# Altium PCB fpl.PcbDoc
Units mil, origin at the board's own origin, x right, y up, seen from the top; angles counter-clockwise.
Board outline 3900 x 3500 mil, 2 copper layers (Top Layer, Bottom Layer); 34 components, 34 nets, 170 pads, 0 vias.
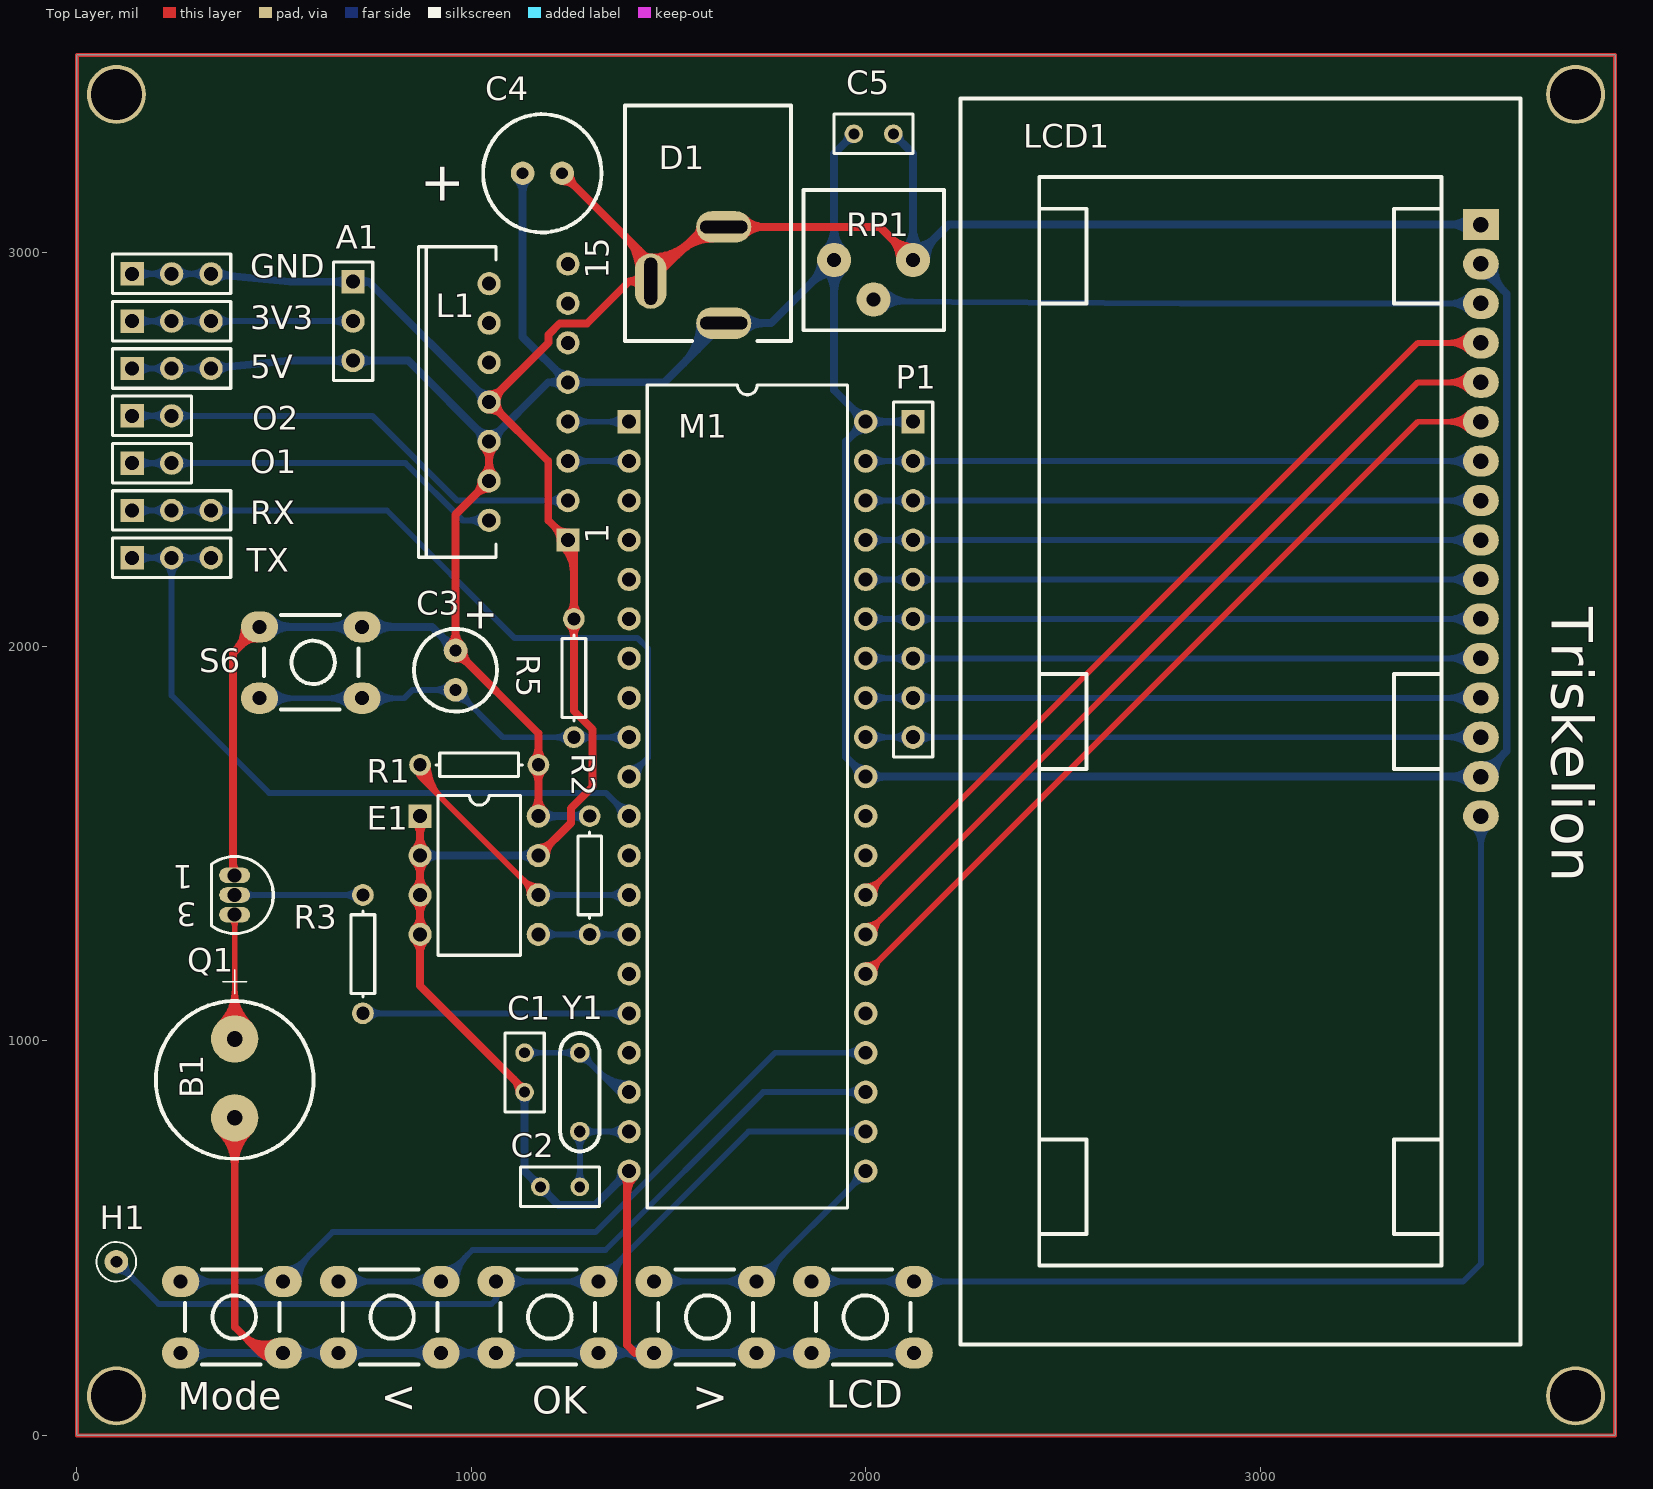
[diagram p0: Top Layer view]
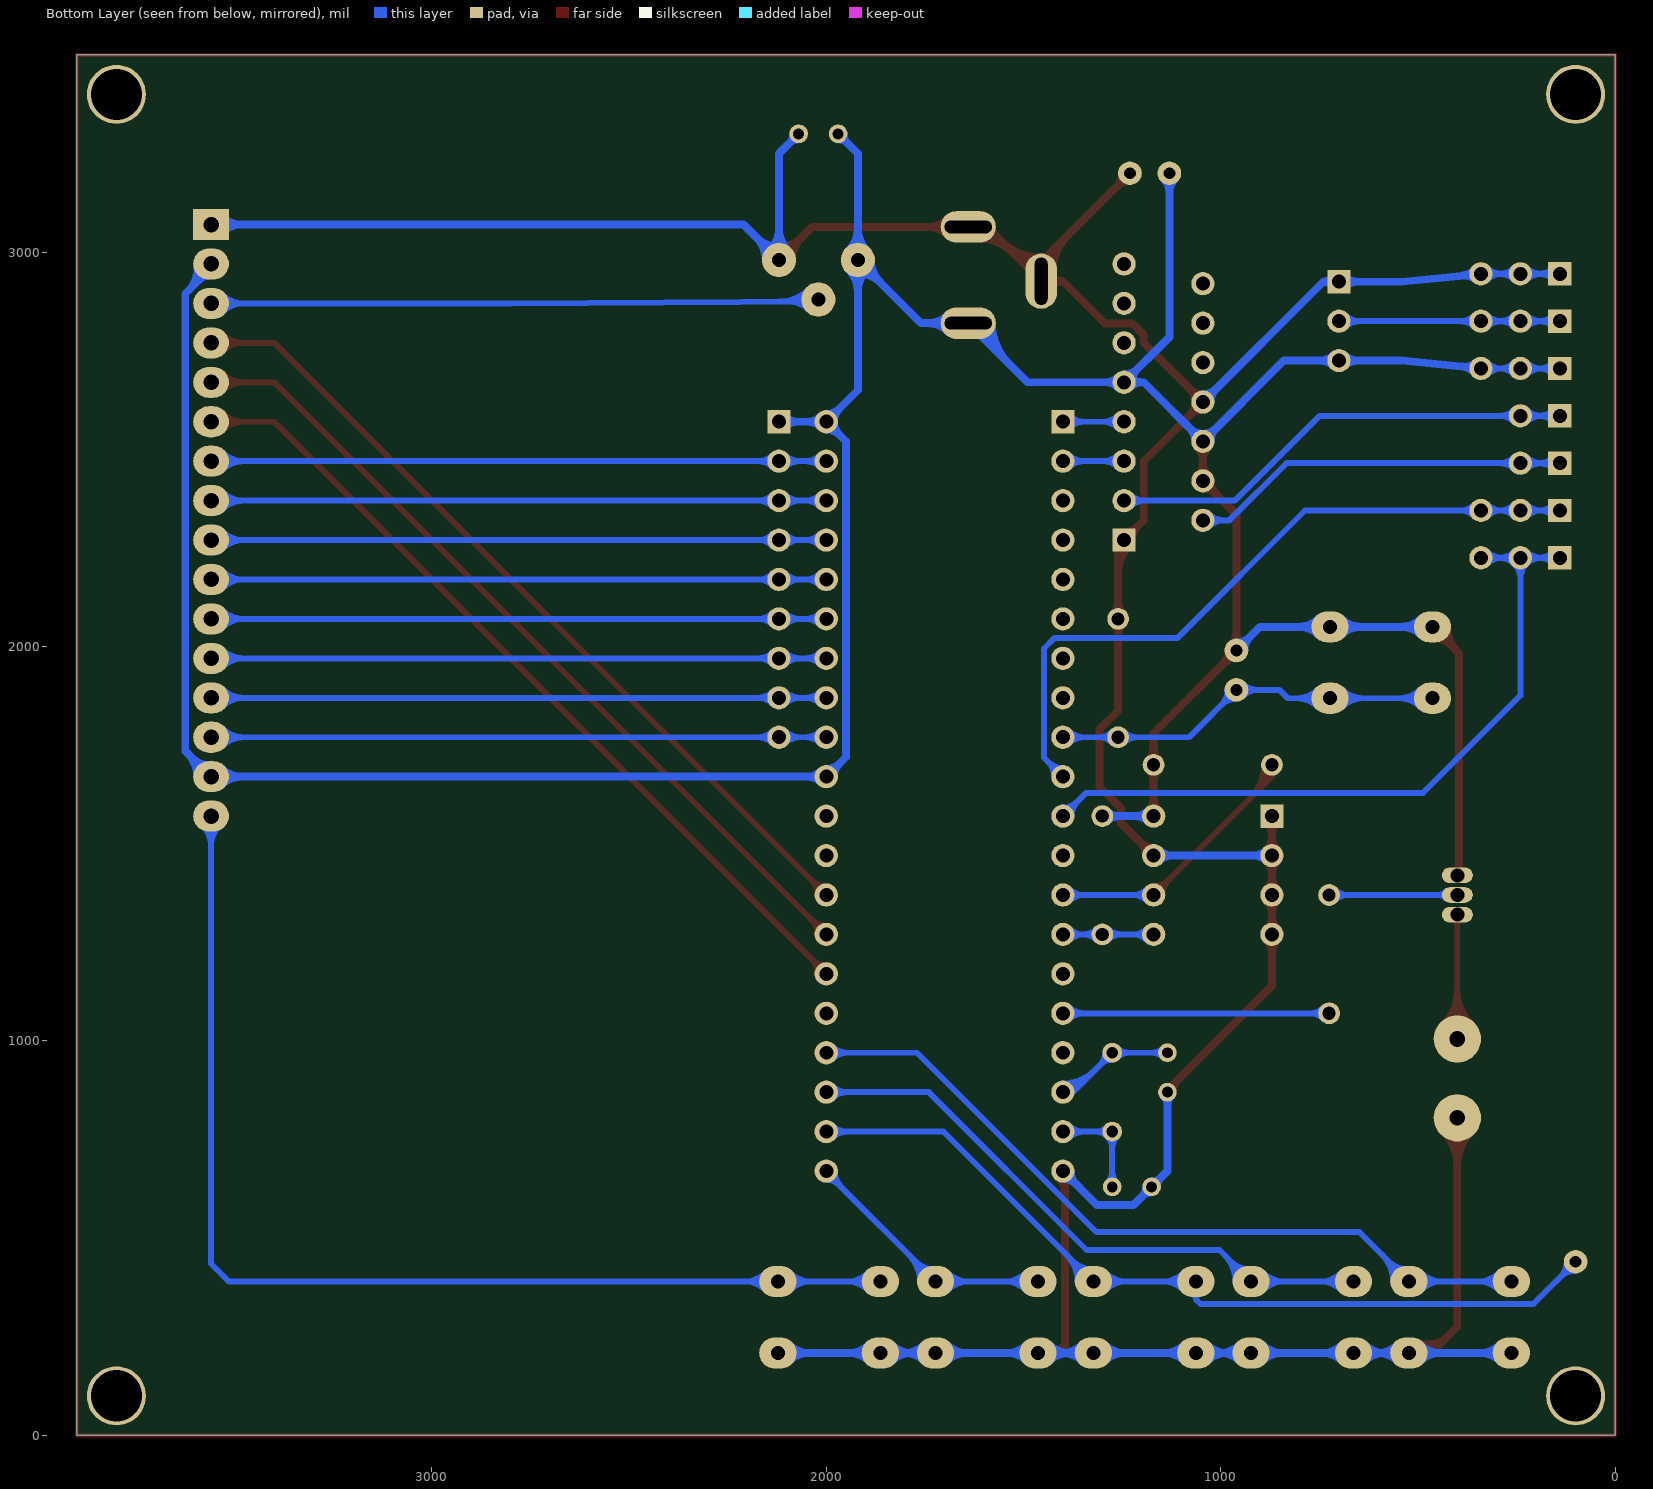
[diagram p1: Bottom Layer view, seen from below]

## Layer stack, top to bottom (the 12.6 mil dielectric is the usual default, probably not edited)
Top Solder: solder mask 0.4, Solder Resist, Dk 3.5
Top Layer: signal copper 1.4
Dielectric1: dielectric 12.6, FR-4, Dk 4.8
Bottom Layer: signal copper 1.4
Bottom Solder: solder mask 0.4, Solder Resist, Dk 3.5

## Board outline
0,0 3900,0 3900,3500 0,3500

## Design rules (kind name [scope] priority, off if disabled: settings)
Clearance [All] p1: gap=10 ignorepadtopadclearanceinfootprint=FALSE except(0: Arc-Hole Track-Hole SMDPad-Hole THPad-Hole Via-Hole Fill-Hole Poly-Hole Region-Hole Text-Hole)
HoleSize [All] p1 off: absolutevalues=TRUE maxlimit=100 minlimit=1 maxpercent=80.000 minpercent=20.000
MinimumSolderMaskSliver [All] p1 off: minsoldermaskwidth=10
PolygonConnect [All] p1: connectstyle=Relief reliefconductorwidth=10 reliefentries=4 polygonreliefangle="90 Angle" airgapwidth=10
RoutingVias [All] p1: holewidth=28 width=50 viastyle="Through Hole" minholewidth=28 minwidth=50 maxholewidth=28 maxwidth=50
SilkToSolderMaskClearance SilkscreenOverComponentPads [IsPad] p1: minsilkscreentomaskgap=5 clearancetoexposedcopper=TRUE
SolderMaskExpansion [All] p1: expansion=4
Width GND [InNet('GND')] p1: maxlimit=25 minlimit=15 preferedwidth=20
Width VCC [InNet('VCC')] p2: maxlimit=25 minlimit=15 preferedwidth=20
Width [All] p3: maxlimit=20 minlimit=10 preferedwidth=15
27 further rules are at their usual default settings.

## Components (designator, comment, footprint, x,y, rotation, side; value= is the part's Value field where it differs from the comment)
3V3 "Header 3" HDR1X3 140,2825 r0 top (schematic designator P3)
5V "Header 3" HDR1X3 140,2705 r0 top (schematic designator P2)
< "switch" switch_4pin 800,300 r0 top (schematic designator S3)
> "switch" switch_4pin 1600,300 r0 top (schematic designator S1)
A1 "3V3" HDR1X3 700,2925 r270 top
B1 "BEEP" BEEP 400,905 r90 top
C1 "Cap" RAD-0.1 1135,920 r90 top
C2 "Cap" RAD-0.1 1225,630 r0 top
C3 "Cap Pol1" ElecCap 960,1940 r180 top
C4 "Cap Pol1" ElecCap470 1180,3200 r90 top
C5 "Cap" RAD-0.1 2020,3300 r0 top
D1 "DC" DC005 1640,3020 r270 top
E1 "E2PROM" DIP-8 1020,1420 r0 top
GND "Header 3" HDR1X3 140,2945 r0 top (schematic designator P4)
H1 "Head1" Head1 100,440 r0 top
L1 "L298N" Multiwatt15V 1145,2620 r90 top
LCD "switch" switch_4pin 2000,300 r0 top (schematic designator S5)
LCD1 "LCD1602" 1602 3560,3070 r270 top
M1 "STC89C52(RC)" 40P6 1700,1620 r270 top
Mode "switch" switch_4pin 400,300 r0 top (schematic designator S4)
O1 "Header 2" HDR1X2 140,2465 r0 top (schematic designator P7)
O2 "Header 2" HDR1X2 140,2585 r0 top (schematic designator P8)
OK "switch" switch_4pin 1200,300 r0 top (schematic designator S2)
P1 "9PIN8" HDR1X9 2120,2570 r270 top
Q1 "2N3906" BCY-W3/E4 400,1370 r180 top
R1 "Res2" AXIAL-0.3 1020,1700 r0 top
R2 "Res2" AXIAL-0.3 1300,1420 r90 top
R3 "Res2" AXIAL-0.3 725,1220 r90 top
R5 "Res2" AXIAL-0.3 1260,1920 r270 top
RP1 "potentiometer" potentionmeter 2020,2980 r0 top
RX "Header 3" HDR1X3 140,2345 r0 top (schematic designator P6)
S6 "switch" switch_4pin 600,1960 r0 top
TX "Header 3" HDR1X3 140,2225 r0 top (schematic designator P5)
Y1 "XTAL" XTAL 1275,870 r270 top

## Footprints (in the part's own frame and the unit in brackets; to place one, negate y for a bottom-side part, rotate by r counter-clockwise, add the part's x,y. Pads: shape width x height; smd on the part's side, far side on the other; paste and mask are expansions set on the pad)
40P6 [mm] "DIP; 40 Leads; Row Spacing 15.24 mm; Pitch 2.54 mm"
  rect 1.5x1.5 hole 0.9: 1(-24.13,-7.62)
  round 1.5 hole 0.9: 2(-21.59,-7.62) 3(-19.05,-7.62) 4(-16.51,-7.62) 5(-13.97,-7.62) 6(-11.43,-7.62) 7(-8.89,-7.62) 8(-6.35,-7.62) 9(-3.81,-7.62) 10(-1.27,-7.62) 11(1.27,-7.62) 12(3.81,-7.62) 13(6.35,-7.62) 14(8.89,-7.62) 15(11.43,-7.62) 16(13.97,-7.62) 17(16.51,-7.62) 18(19.05,-7.62) 19(21.59,-7.62) 20(24.13,-7.62) 21(24.13,7.62) 22(21.59,7.62) 23(19.05,7.62) 24(16.51,7.62) 25(13.97,7.62) 26(11.43,7.62) 27(8.89,7.62) 28(6.35,7.62) 29(3.81,7.62) 30(1.27,7.62) 31(-1.27,7.62) 32(-3.81,7.62) 33(-6.35,7.62) 34(-8.89,7.62) 35(-11.43,7.62) 36(-13.97,7.62) 37(-16.51,7.62) 38(-19.05,7.62) 39(-21.59,7.62) 40(-24.13,7.62)
  silkscreen extent -26.5,-6.45 26.5,6.45
1602 [mm]
  rect 2x2.3 hole 1: 1(0,0)
  oval 2x2.3 hole 1: 2(2.54,0) 3(5.08,0) 4(7.62,0) 5(10.16,0) 6(12.7,0) 7(15.24,0) 8(17.78,0) 9(20.32,0) 10(22.86,0) 11(25.4,0) 12(27.94,0) 13(30.48,0) 14(33.02,0) 15(35.56,0) 16(38.1,0)
  silkscreen extent -8.13,-33.53 72.14,2.54
AXIAL-0.3 [mm] "Axial Device, Thru-Hole; 2 Leads; 0.3 in Pin Spacing"
  round 1.4 hole 0.85: 1(-3.81,0) 2(3.81,0)
  silkscreen extent -2.77,-0.76 2.77,0.76
BCY-W3/E4 [mm] "TO, Flat Index; 3 In-Line, Axial Leads; Body Dia. 4.5mm; Leads 0.51 x 0.48 mm (max)"
  oval 2x1 hole 0.9: 1(0,-1.27) 2(0,0) 3(0,1.27)
  silkscreen extent -2.48,-2.48 1.5,2.48
BEEP [mil] "蜂鸣器"
  round 120 hole 40: 1(100,0) 2(-100,0)
  silkscreen extent -204,-200 275,200
DC005 [mil] "2.1mmDC插座"
  oval 80x140 hole 32 slot 120 at 90 deg: 1(200,0) 3(-44,0)
  oval 140x80 hole 32 slot 120 at 0 deg: 2(93.7,-185)
  silkscreen extent -352,-250 245,170
DIP-8 [mm]
  rect 1.5x1.5 hole 0.9: 1(-3.81,3.81)
  round 1.5 hole 0.9: 2(-3.81,1.27) 3(-3.81,-1.27) 4(-3.81,-3.81) 5(3.81,-3.81) 6(3.81,-1.27) 7(3.81,1.27) 8(3.81,3.81)
  silkscreen extent -2.65,-5.15 2.65,5.15
ElecCap [mil] "10uF电解电容"
  round 60 hole 30: 1(0,-50) 2(0,50)
  silkscreen extent -105,-105 105,105
ElecCap470 [mil] "470uF电解电容"
  round 60 hole 30: 1(0,50) 2(0,-50)
  silkscreen extent -150,-150 150,150
HDR1X2 [mm] "Connector; Header; 2 Position"
  rect 1.5x1.5 hole 0.9: 1(0,0)
  round 1.5 hole 0.9: 2(2.54,0)
  silkscreen extent -1.27,-1.27 3.81,1.27
HDR1X3 [mm] "Connector; Header; 3 Position"
  rect 1.5x1.5 hole 0.9: 1(0,0)
  round 1.5 hole 0.9: 2(2.54,0) 3(5.08,0)
  silkscreen extent -1.27,-1.27 6.35,1.27
HDR1X9 [mm] "Connector; Header; 9 Position"
  rect 1.5x1.5 hole 0.9: 1(0,0)
  round 1.5 hole 0.9: 2(2.54,0) 3(5.08,0) 4(7.62,0) 5(10.16,0) 6(12.7,0) 7(15.24,0) 8(17.78,0) 9(20.32,0)
  silkscreen extent -1.27,-1.27 21.59,1.27
Head1 [mil] "1pin焊盘"
  round 60 hole 30: 1(0,0)
  silkscreen extent -50,-50 50,50
Multiwatt15V [mm] "TO, Thru-Hole, Vertical, Heatsink Mounted; 15 Bent Staggered Leads; Pitch 1.27 mm"
  rect 1.5x1.5 hole 0.9: 1(-8.89,-2.54)
  round 1.5 hole 0.9: 2(-7.62,2.54) 3(-6.35,-2.54) 4(-5.08,2.54) 5(-3.81,-2.54) 6(-2.54,2.54) 7(-1.27,-2.54) 8(0,2.54) 9(1.27,-2.54) 10(2.54,2.54) 11(3.81,-2.54) 12(5.08,2.54) 13(6.35,-2.54) 14(7.62,2.54) 15(8.89,-2.54)
  silkscreen extent -10,2.09 10,7.09
potentionmeter [mm] "电位计"
  round 2.2 hole 0.9: 1(-2.54,0) 2(0,-2.54) 3(2.54,0)
  silkscreen extent -4.52,-4.52 4.52,4.52
RAD-0.1 [mm] "Radial Cap, Thru-Hole; 2 Leads; 0.1 in Pin Spacing"
  round 1.2 hole 0.7: 1(-1.27,0) 2(1.27,0)
  silkscreen extent -2.54,-1.27 2.54,1.27
switch_4pin [mm] "单稳态按钮开关"
  oval 2.4x2 hole 0.9: 0(-3.48,2.286) 1(-3.48,-2.314) 2(3.12,2.286) 3(3.12,-2.314)
  silkscreen extent -3.2,-3.05 2.9,3.05
XTAL [mil] "晶振"
  round 50 hole 30: 1(-100,0) 2(100,0)
  silkscreen extent -150,-50 150,50

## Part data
3V3 5V GND RX TX: "Header, 3-Pin"
< > LCD Mode OK S6: library part Switch_4pin, "单稳态按钮开关"
A1: library part AMS1117, "3.3V电源模块, 5V to 3.3V"
B1: "蜂鸣器"
C1 C2 C5: "Capacitor"
C3 C4: "Polarized Capacitor (Radial)"
D1: "DC插座"
E1: library part AT24C02, "E2PROM,I2C-上拉"
H1: "1pin焊盘"
L1: "电机驱动芯片"
M1: library part STC89C52, "MCU"
O1 O2: "Header, 2-Pin"
P1: "9PIN8排阻"
Q1: "PNP General Purpose Amplifier"
R1 R2 R3 R5: "Resistor"
RP1: library part 电位计, "旋钮式电位计"
Y1: "Crystal Oscillator"

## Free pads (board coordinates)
  round 150 hole 130: 0(100,100) 0(100,3400) 0(3800,100) 0(3800,3400)

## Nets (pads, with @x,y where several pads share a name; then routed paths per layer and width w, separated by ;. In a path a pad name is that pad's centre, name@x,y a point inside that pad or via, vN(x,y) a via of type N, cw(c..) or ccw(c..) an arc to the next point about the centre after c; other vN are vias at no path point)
BEEP: M1.16 R3.1 | length 834.6
  Bottom Layer w15: R3.1 M1.16 ; R3.1@739.18,1055.82 cw(c773.43,1021.57) 773.43,1070 cw(c773.43,1118.43) R3.1@739.18,1084.18 ; M1.16@1384.42,1054.42 ccw(c1346.82,1016.82) 1346.82,1070 ccw(c1346.82,1123.18) M1.16@1384.42,1085.58
D0: LCD1.7 M1.39 P1.2 | length 1995.4
  Bottom Layer w15: M1.39 P1.2 LCD1.7 ; M1.39@2015.58,2454.42 cw(c2053.18,2416.82) 2053.18,2470 cw(c2053.18,2523.18) M1.39@2015.58,2485.58 ; P1.2@2104.42,2454.42 ccw(c2066.82,2416.82) 2066.82,2470 ccw(c2066.82,2523.18) P1.2@2104.42,2485.58 ; P1.2@2135.58,2454.42 cw(c2173.18,2416.82) 2173.18,2470 cw(c2173.18,2523.18) P1.2@2135.58,2485.58 ; LCD1.7@3531.56,2447.46 ccw(c3477.15,2393.06) 3477.15,2470 ccw(c3477.15,2546.94) LCD1.7@3531.56,2492.54 ; LCD1.7@3542.17,2458.07 ccw(c3513.37,2429.27) 3513.37,2470 ccw(c3513.37,2510.73) LCD1.7@3542.17,2481.93
D1: LCD1.8 M1.38 P1.3 | length 1995.4
  Bottom Layer w15: M1.38 P1.3 LCD1.8 ; M1.38@2015.58,2354.42 cw(c2053.18,2316.82) 2053.18,2370 cw(c2053.18,2423.18) M1.38@2015.58,2385.58 ; P1.3@2104.42,2354.42 ccw(c2066.82,2316.82) 2066.82,2370 ccw(c2066.82,2423.18) P1.3@2104.42,2385.58 ; P1.3@2135.58,2354.42 cw(c2173.18,2316.82) 2173.18,2370 cw(c2173.18,2423.18) P1.3@2135.58,2385.58 ; LCD1.8@3531.56,2347.46 ccw(c3477.15,2293.06) 3477.15,2370 ccw(c3477.15,2446.94) LCD1.8@3531.56,2392.54 ; LCD1.8@3542.17,2358.07 ccw(c3513.37,2329.27) 3513.37,2370 ccw(c3513.37,2410.73) LCD1.8@3542.17,2381.93
D2: LCD1.9 M1.37 P1.4 | length 1995.4
  Bottom Layer w15: M1.37 P1.4 LCD1.9 ; M1.37@2015.58,2254.42 cw(c2053.18,2216.82) 2053.18,2270 cw(c2053.18,2323.18) M1.37@2015.58,2285.58 ; P1.4@2104.42,2254.42 ccw(c2066.82,2216.82) 2066.82,2270 ccw(c2066.82,2323.18) P1.4@2104.42,2285.58 ; P1.4@2135.58,2254.42 cw(c2173.18,2216.82) 2173.18,2270 cw(c2173.18,2323.18) P1.4@2135.58,2285.58 ; LCD1.9@3531.56,2247.46 ccw(c3477.15,2193.06) 3477.15,2270 ccw(c3477.15,2346.94) LCD1.9@3531.56,2292.54 ; LCD1.9@3542.17,2258.07 ccw(c3513.37,2229.27) 3513.37,2270 ccw(c3513.37,2310.73) LCD1.9@3542.17,2281.93
D3: LCD1.10 M1.36 P1.5 | length 1995.4
  Bottom Layer w15: M1.36 P1.5 LCD1.10 ; M1.36@2015.58,2154.42 cw(c2053.18,2116.82) 2053.18,2170 cw(c2053.18,2223.18) M1.36@2015.58,2185.58 ; P1.5@2104.42,2154.42 ccw(c2066.82,2116.82) 2066.82,2170 ccw(c2066.82,2223.18) P1.5@2104.42,2185.58 ; P1.5@2135.58,2154.42 cw(c2173.18,2116.82) 2173.18,2170 cw(c2173.18,2223.18) P1.5@2135.58,2185.58 ; LCD1.10@3531.56,2147.46 ccw(c3477.15,2093.06) 3477.15,2170 ccw(c3477.15,2246.94) LCD1.10@3531.56,2192.54 ; LCD1.10@3542.17,2158.07 ccw(c3513.37,2129.27) 3513.37,2170 ccw(c3513.37,2210.73) LCD1.10@3542.17,2181.93
D4: LCD1.11 M1.35 P1.6 | length 1995.4
  Bottom Layer w15: M1.35 P1.6 LCD1.11 ; M1.35@2015.58,2054.42 cw(c2053.18,2016.82) 2053.18,2070 cw(c2053.18,2123.18) M1.35@2015.58,2085.58 ; P1.6@2104.42,2054.42 ccw(c2066.82,2016.82) 2066.82,2070 ccw(c2066.82,2123.18) P1.6@2104.42,2085.58 ; P1.6@2135.58,2054.42 cw(c2173.18,2016.82) 2173.18,2070 cw(c2173.18,2123.18) P1.6@2135.58,2085.58 ; LCD1.11@3531.56,2047.46 ccw(c3477.15,1993.06) 3477.15,2070 ccw(c3477.15,2146.94) LCD1.11@3531.56,2092.54 ; LCD1.11@3542.17,2058.07 ccw(c3513.37,2029.27) 3513.37,2070 ccw(c3513.37,2110.73) LCD1.11@3542.17,2081.93
D5: LCD1.12 M1.34 P1.7 | length 1995.4
  Bottom Layer w15: M1.34 P1.7 LCD1.12 ; M1.34@2015.58,1954.42 cw(c2053.18,1916.82) 2053.18,1970 cw(c2053.18,2023.18) M1.34@2015.58,1985.58 ; P1.7@2104.42,1954.42 ccw(c2066.82,1916.82) 2066.82,1970 ccw(c2066.82,2023.18) P1.7@2104.42,1985.58 ; P1.7@2135.58,1954.42 cw(c2173.18,1916.82) 2173.18,1970 cw(c2173.18,2023.18) P1.7@2135.58,1985.58 ; LCD1.12@3531.56,1947.46 ccw(c3477.15,1893.06) 3477.15,1970 ccw(c3477.15,2046.94) LCD1.12@3531.56,1992.54 ; LCD1.12@3542.17,1958.07 ccw(c3513.37,1929.27) 3513.37,1970 ccw(c3513.37,2010.73) LCD1.12@3542.17,1981.93
D6: LCD1.13 M1.33 P1.8 | length 1995.4
  Bottom Layer w15: M1.33 P1.8 LCD1.13 ; M1.33@2015.58,1854.42 cw(c2053.18,1816.82) 2053.18,1870 cw(c2053.18,1923.18) M1.33@2015.58,1885.58 ; P1.8@2104.42,1854.42 ccw(c2066.82,1816.82) 2066.82,1870 ccw(c2066.82,1923.18) P1.8@2104.42,1885.58 ; P1.8@2135.58,1854.42 cw(c2173.18,1816.82) 2173.18,1870 cw(c2173.18,1923.18) P1.8@2135.58,1885.58 ; LCD1.13@3531.56,1847.46 ccw(c3477.15,1793.06) 3477.15,1870 ccw(c3477.15,1946.94) LCD1.13@3531.56,1892.54 ; LCD1.13@3542.17,1858.07 ccw(c3513.37,1829.27) 3513.37,1870 ccw(c3513.37,1910.73) LCD1.13@3542.17,1881.93
D7: LCD1.14 M1.32 P1.9 | length 1995.4
  Bottom Layer w15: M1.32 P1.9 LCD1.14 ; M1.32@2015.58,1754.42 cw(c2053.18,1716.82) 2053.18,1770 cw(c2053.18,1823.18) M1.32@2015.58,1785.58 ; P1.9@2104.42,1754.42 ccw(c2066.82,1716.82) 2066.82,1770 ccw(c2066.82,1823.18) P1.9@2104.42,1785.58 ; P1.9@2135.58,1754.42 cw(c2173.18,1716.82) 2173.18,1770 cw(c2173.18,1823.18) P1.9@2135.58,1785.58 ; LCD1.14@3531.56,1747.46 ccw(c3477.15,1693.06) 3477.15,1770 ccw(c3477.15,1846.94) LCD1.14@3531.56,1792.54 ; LCD1.14@3542.17,1758.07 ccw(c3513.37,1729.27) 3513.37,1770 ccw(c3513.37,1810.73) LCD1.14@3542.17,1781.93
GND: <.1 <.3 >.1 >.3 A1.1 B1.2 C1.1 C2.1 C4.2 C5.2 D1.2 D1.3 E1.1 E1.2 E1.3 E1.4 E1.7 GND.1 GND.2 GND.3 L1.1 L1.8 LCD1.1 LCD.1 LCD.3 M1.20 Mode.1 Mode.3 OK.1 OK.3 R5.1 RP1.3 | length 16660.4
  Top Layer w20: B1.2@364.64,769.64 cw(c279.29,684.29) 400,684.29 cw(c520.71,684.29) B1.2@435.36,769.64 ; B1.2@378.79,783.79 cw(c327.57,732.57) 400,732.57 cw(c472.43,732.57) B1.2@421.21,783.79 ; B1.2 400,275 466.1,208.9 ; 424.44,250.56 ccw(c474.6,300.73) Mode.3@503.15,235.78 ; 445.12,229.88 ccw(c487.23,272) Mode.3@511.2,217.48 ; 465.8,209.2 ccw(c499.86,243.27) Mode.3@519.25,199.17 ; Mode.3@489.03,195.12 ccw(c466.1,182.93) 466.1,208.9 ; Mode.3@489.03,222.68 cw(c466.1,234.86) 466.1,208.9 ; Mode.3 466.1,208.9 ; E1.4@856.19,1256.19 cw(c822.86,1222.86) 870,1222.86 cw(c917.14,1222.86) E1.4@883.81,1256.19 ; E1.4@856.19,1283.81 ccw(c822.86,1317.14) 870,1317.14 ccw(c917.14,1317.14) E1.4@883.81,1283.81 ; E1.3@856.19,1356.19 cw(c822.86,1322.86) 870,1322.86 cw(c917.14,1322.86) E1.3@883.81,1356.19 ; E1.3@856.19,1383.81 ccw(c822.86,1417.14) 870,1417.14 ccw(c917.14,1417.14) E1.3@883.81,1383.81 ; E1.2@856.19,1456.19 cw(c822.86,1422.86) 870,1422.86 cw(c917.14,1422.86) E1.2@883.81,1456.19 ; E1.2@856.19,1483.81 ccw(c822.86,1517.14) 870,1517.14 ccw(c917.14,1517.14) E1.2@883.81,1483.81 ; E1.1@856.19,1556.19 cw(c822.86,1522.86) 870,1522.86 cw(c917.14,1522.86) E1.1@883.81,1556.19 ; E1.1 E1.2 E1.3 E1.4 870,1140 C1.1@1140,870 ; L1.8@1045,2600.47 cw(c1045,2553.33) 1078.34,2586.66 cw(c1111.67,2620) 1064.53,2620 cw(c1111.67,2620) 1078.34,2653.34 cw(c1045,2686.67) L1.8@1045,2639.53 ; 1108.21,901.79 cw(c1076.42,870) C1.1@1121.38,870 ; 1120.28,889.72 ccw(c1135,904.44) C1.1@1135,883.62 ; E1.7 1252.44,1552.44 1252.44,1589.7 1307.56,1644.82 1307.56,1789.7 1260,1837.26 R5.1 1260,2255 L1.1 1195,2320 1195,2470 L1.8 1195.47,2770.47 1195.47,2790.51 1224.49,2819.53 1293.58,2819.53 1400.36,2926.3 ; E1.7@1170,1489.53 ccw(c1170,1536.67) 1203.34,1503.34 ccw(c1236.67,1470) E1.7@1189.53,1470 ; L1.1@1225.47,2270 ccw(c1178.33,2270) 1211.66,2303.34 ccw(c1245,2336.67) L1.1@1245,2289.53 ; C4.2@1230,3180 cw(c1230,3131.72) 1264.14,3165.86 cw(c1298.28,3200) C4.2@1250,3200 ; C4.2 1455,2975 D1.2 ; L1.1@1231.19,2256.19 cw(c1161.64,2186.64) 1260,2186.64 ; L1.1@1245.33,2270.33 cw(c1209.93,2234.93) 1260,2234.93 ; R5.1@1247.58,2057.58 cw(c1217.61,2027.61) 1260,2027.61 cw(c1302.39,2027.61) R5.1@1272.42,2057.58 ; R5.1@1247.58,2082.42 ccw(c1217.61,2112.39) 1260,2112.39 ccw(c1302.39,2112.39) R5.1@1272.42,2082.42 ; M1.20@1386.19,656.19 cw(c1364.93,634.93) 1395,634.93 ; 1390.56,3039.44 cw(c1307.43,2956.3) D1.2@1425,2956.3 ; 1395,610.79 cw(c1459.21,610.79) M1.20@1413.81,656.19 ; M1.20 1395,665 1395,228.9 1415,208.9 >.1 ; 1424.71,3005.29 cw(c1375.71,2956.3) D1.2@1445,2956.3 ; D1.2@1429.69,2910.2 ccw(c1400.36,2891.54) 1400.36,2926.3 ; D1.2@1429.69,2942.4 cw(c1400.36,2961.06) 1400.36,2926.3 ; 1435.71,2994.29 ccw(c1455,3013.58) 1455,2986.3 ccw(c1455,3131.15) 1557.43,3028.73 ; D1.2@1455,2966.3 ccw(c1455,3062.87) 1523.28,2994.58 ; 1529.25,3000.55 cw(c1610,2919.81) D1.3@1610,3034 ; 1563.4,3034.7 cw(c1610,2988.09) D1.3@1610,3054 ; 1571.02,3042.32 ccw(c1549.34,3064) D1.3@1580,3064 ; D1.3@1691.21,3042.79 cw(c1742.43,2991.57) 1742.43,3064 cw(c1742.43,3136.43) D1.3@1691.21,3085.21 ; RP1.3@2086.69,2980 ccw(c2006.28,2980) 2063.14,3036.86 ccw(c2120,3093.72) RP1.3@2120,3013.31 ; RP1.3 2036,3064 D1.3 1592.7,3064 D1.2 ; 1400.36,2926.3 D1.2
  Bottom Layer w15: GND.1 GND.2 GND.3@320,2945 ; GND.1@155.58,2929.42 cw(c193.18,2891.82) 193.18,2945 cw(c193.18,2998.18) GND.1@155.58,2960.58 ; GND.2@224.42,2929.42 ccw(c186.82,2891.82) 186.82,2945 ccw(c186.82,2998.18) GND.2@224.42,2960.58 ; GND.2@255.58,2929.42 cw(c293.18,2891.82) 293.18,2945 cw(c293.18,2998.18) GND.2@255.58,2960.58 ; GND.3@324.42,2929.42 ccw(c286.82,2891.82) 286.82,2945 ccw(c286.82,2998.18) GND.3@324.42,2960.58
  Bottom Layer w20: Mode.1 Mode.3 <.1 <.3 OK.1 OK.3 >.1 >.3 LCD.1 LCD.3 ; Mode.1@291.64,188.13 cw(c341.78,137.99) 341.78,208.9 cw(c341.78,279.8) Mode.1@291.64,229.67 ; GND.3@320,2945 GND.3 540,2925 A1.1 740,2925 ; GND.3@352.37,2929.89 cw(c382.22,2893.4) 386.91,2940.31 cw(c391.6,2987.22) GND.3@355.11,2957.37 ; Mode.3@494.2,188.13 ccw(c444.06,137.99) 444.06,208.9 ccw(c444.06,279.8) Mode.3@494.2,229.67 ; Mode.3@551.48,188.13 cw(c601.62,137.99) 601.62,208.9 cw(c601.62,279.8) Mode.3@551.48,229.67 ; <.1@634.36,188.13 ccw(c584.22,137.99) 584.22,208.9 ccw(c584.22,279.8) <.1@634.36,229.67 ; A1.1@686.19,2911.19 ccw(c652.86,2877.86) 652.86,2925 ccw(c652.86,2972.14) A1.1@686.19,2938.81 ; <.1@691.64,188.13 cw(c741.78,137.99) 741.78,208.9 cw(c741.78,279.8) <.1@691.64,229.67 ; A1.1@715.4,2912.99 cw(c740,2893.8) 740,2925 ; A1.1@715.4,2937.01 ccw(c740,2956.2) 740,2925 ; E1.2 E1.7 ; E1.2@883.81,1456.19 cw(c917.14,1422.86) 917.14,1470 cw(c917.14,1517.14) E1.2@883.81,1483.81 ; <.3@894.2,188.13 ccw(c844.06,137.99) 844.06,208.9 ccw(c844.06,279.8) <.3@894.2,229.67 ; <.3@951.48,188.13 cw(c1001.62,137.99) 1001.62,208.9 cw(c1001.62,279.8) <.3@951.48,229.67 ; L1.8@1025.47,2620 ccw(c978.33,2620) 1011.66,2653.34 ccw(c1045,2686.67) L1.8@1045,2639.53 ; OK.1@1034.36,188.13 ccw(c984.22,137.99) 984.22,208.9 ccw(c984.22,279.8) OK.1@1034.36,229.67 ; L1.8 740,2925 ; OK.1@1091.64,188.13 cw(c1141.78,137.99) 1141.78,208.9 cw(c1141.78,279.8) OK.1@1091.64,229.67 ; C1.1@1125.37,860.37 cw(c1102.11,837.11) 1135,837.11 cw(c1167.89,837.11) C1.1@1144.63,860.37 ; C1.1 1135,670 C2.1 1221,584 1314,584 M1.20 ; E1.7@1156.19,1456.19 ccw(c1122.86,1422.86) 1122.86,1470 ccw(c1122.86,1517.14) E1.7@1156.19,1483.81 ; C2.1@1161.38,630 ccw(c1128.49,630) 1151.75,653.25 ccw(c1175,676.51) C2.1@1175,643.62 ; C2.1@1175,616.38 cw(c1175,583.49) 1198.25,606.75 cw(c1221.51,630) C2.1@1188.62,630 ; OK.3@1294.2,188.13 ccw(c1244.06,137.99) 1244.06,208.9 ccw(c1244.06,279.8) OK.3@1294.2,229.67 ; OK.3@1351.48,188.13 cw(c1401.62,137.99) 1401.62,208.9 cw(c1401.62,279.8) OK.3@1351.48,229.67 ; M1.20@1380.47,670 cw(c1333.33,670) 1366.66,636.66 cw(c1400,603.33) M1.20@1400,650.47 ; >.1@1434.36,188.13 ccw(c1384.22,137.99) 1384.22,208.9 ccw(c1384.22,279.8) >.1@1434.36,229.67 ; D1.2@1455,2895.47 D1.2 ; >.1@1491.64,188.13 cw(c1541.78,137.99) 1541.78,208.9 cw(c1541.78,279.8) >.1@1491.64,229.67 ; >.3@1694.2,188.13 ccw(c1644.06,137.99) 1644.06,208.9 ccw(c1644.06,279.8) >.3@1694.2,229.67 ; >.3@1751.48,188.13 cw(c1801.62,137.99) 1801.62,208.9 cw(c1801.62,279.8) >.3@1751.48,229.67 ; LCD.1@1834.36,188.13 ccw(c1784.22,137.99) 1784.22,208.9 ccw(c1784.22,279.8) LCD.1@1834.36,229.67 ; LCD.1@1891.64,188.13 cw(c1941.78,137.99) 1941.78,208.9 cw(c1941.78,279.8) LCD.1@1891.64,229.67 ; C5.2@2070,3286.38 cw(c2070,3253.49) 2093.25,3276.75 cw(c2116.51,3300) C5.2@2083.62,3300 ; C5.2 2120,3250 RP1.3 2210,3070 LCD1.1 ; LCD.3@2094.2,188.13 ccw(c2044.06,137.99) 2044.06,208.9 ccw(c2044.06,279.8) LCD.3@2094.2,229.67 ; RP1.3@2096.45,3003.55 ccw(c2039.59,3060.41) 2120,3060.41 ccw(c2200.41,3060.41) RP1.3@2143.55,3003.55 ; RP1.3@2120,3013.31 ccw(c2120,3093.72) 2176.86,3036.86 ccw(c2233.72,2980) RP1.3@2153.31,2980 ; LCD1.1@3533.33,3049.23 ccw(c3483.19,2999.09) 3483.19,3070 ccw(c3483.19,3140.91) LCD1.1@3533.33,3090.77
NetB1_1: B1.1 Q1.3 | length 702.5
  Top Layer w15: B1.1@362.88,1042.12 ccw(c273.25,1131.75) 400,1131.75 ccw(c526.75,1131.75) B1.1@437.12,1042.12 ; B1.1@373.48,1031.52 ccw(c309.47,1095.53) 400,1095.53 ccw(c490.53,1095.53) B1.1@426.52,1031.52 ; Q1.3@391.38,1311.38 cw(c370.58,1290.58) 400,1290.58 cw(c429.42,1290.58) Q1.3@408.62,1311.38 ; B1.1 Q1.3
NetC1_2: C1.2 M1.18 Y1.1 | length 645.2
  Bottom Layer w15: C1.2@1140,970 Y1.1 1375,870 M1.18 ; C1.2@1146.4,958.6 cw(c1173.92,931.08) 1173.92,970 cw(c1173.92,1008.92) C1.2@1146.4,981.4 ; Y1.1@1262.63,957.63 ccw(c1232.75,927.75) 1232.75,970 ccw(c1232.75,1012.25) Y1.1@1262.63,982.37 ; Y1.1@1275,952.5 cw(c1275,910.25) 1304.87,940.13 cw(c1334.75,970) Y1.1@1292.5,970 ; 1319.72,925.28 ccw(c1400,1005.56) M1.18@1400,892.03 ; 1345.33,899.67 ccw(c1400,954.35) M1.18@1400,877.03
NetC2_2: C2.2 M1.19 Y1.2 | length 542.4
  Bottom Layer w15: Y1.2@1262.63,757.63 cw(c1232.75,727.75) 1275,727.75 cw(c1317.25,727.75) 1287.37,757.63 cw(c1317.25,727.75) 1317.25,770 cw(c1317.25,812.25) Y1.2@1287.37,782.37 ; C2.2@1263.6,641.4 ccw(c1236.08,668.92) 1275,668.92 ccw(c1313.92,668.92) C2.2@1286.4,641.4 ; C2.2 Y1.2 M1.19 ; M1.19@1384.42,754.42 ccw(c1346.82,716.82) 1346.82,770 ccw(c1346.82,823.18) M1.19@1384.42,785.58
NetH1_1: H1.1 M1.22 OK.0 OK.2 | length 2897
  Bottom Layer w15: H1.1@100,417.5 cw(c100,363.18) 138.41,401.59 cw(c176.82,440) H1.1@122.5,440 ; H1.1 207,333 1051,333 1063,345 ; OK.0@1052.42,359.94 cw(c1047.17,345) 1063,345 ; OK.0@1073.58,359.94 ccw(c1078.83,345) 1063,345 ; OK.0@1082.8,378.07 cw(c1111.6,349.27) 1111.6,390 cw(c1111.6,430.73) OK.0@1082.8,401.93 ; OK.0@1093.41,367.46 cw(c1147.82,313.06) 1147.82,390 cw(c1147.82,466.94) OK.0@1093.41,412.54 ; OK.2@1292.43,367.46 ccw(c1238.03,313.06) 1238.03,390 ccw(c1238.03,466.94) OK.2@1292.43,412.54 ; OK.2@1303.04,378.07 ccw(c1274.24,349.27) 1274.24,390 ccw(c1274.24,430.73) OK.2@1303.04,401.93 ; OK.2@1330.72,421.87 ccw(c1330.72,479.8) 1371.68,438.84 ; OK.2@1347.59,390 cw(c1407.32,390) 1365.08,432.24 ; OK.2@1362.59,390 cw(c1458.54,390) 1390.69,457.85 ; M1.22@1984.42,754.42 ccw(c1946.82,716.82) 1946.82,770 ccw(c1946.82,823.18) M1.22@1984.42,785.58 ; M1.22 1702.84,770 OK.2 OK.0 1063,345
NetL1_5: L1.5 M1.2 | length 322.1
  Bottom Layer w15: L1.5 M1.2 ; L1.5@1260.58,2454.42 cw(c1298.18,2416.82) 1298.18,2470 cw(c1298.18,2523.18) L1.5@1260.58,2485.58 ; M1.2@1384.42,2454.42 ccw(c1346.82,2416.82) 1346.82,2470 ccw(c1346.82,2523.18) M1.2@1384.42,2485.58
NetL1_7: L1.7 M1.1 | length 322.1
  Bottom Layer w15: L1.7 M1.1 ; L1.7@1260.58,2554.42 cw(c1298.18,2516.82) 1298.18,2570 cw(c1298.18,2623.18) L1.7@1260.58,2585.58 ; M1.1@1384.42,2554.42 ccw(c1346.82,2516.82) 1346.82,2570 ccw(c1346.82,2623.18) M1.1@1384.42,2585.58
NetLCD1_4: LCD1.4 M1.28 | length 2408.3
  Top Layer w15: M1.28 3400,2770 LCD1.4 ; M1.28@2000,1392.03 ccw(c2000,1445.21) 2037.6,1407.6 ccw(c2075.21,1370) M1.28@2022.03,1370 ; LCD1.4@3531.56,2747.46 ccw(c3477.15,2693.06) 3477.15,2770 ccw(c3477.15,2846.94) LCD1.4@3531.56,2792.54 ; LCD1.4@3542.17,2758.07 ccw(c3513.37,2729.27) 3513.37,2770 ccw(c3513.37,2810.73) LCD1.4@3542.17,2781.93
NetLCD1_5: LCD1.5 M1.27 | length 2408.3
  Top Layer w15: M1.27 3400,2670 LCD1.5 ; M1.27@2000,1292.03 ccw(c2000,1345.21) 2037.6,1307.6 ccw(c2075.21,1270) M1.27@2022.03,1270 ; LCD1.5@3531.56,2647.46 ccw(c3477.15,2593.06) 3477.15,2670 ccw(c3477.15,2746.94) LCD1.5@3531.56,2692.54 ; LCD1.5@3542.17,2658.07 ccw(c3513.37,2629.27) 3513.37,2670 ccw(c3513.37,2710.73) LCD1.5@3542.17,2681.93
NetLCD1_6: LCD1.6 M1.26 | length 2408.3
  Top Layer w15: M1.26 3400,2570 LCD1.6 ; M1.26@2000,1192.03 ccw(c2000,1245.21) 2037.6,1207.6 ccw(c2075.21,1170) M1.26@2022.03,1170 ; LCD1.6@3531.56,2547.46 ccw(c3477.15,2493.06) 3477.15,2570 ccw(c3477.15,2646.94) LCD1.6@3531.56,2592.54 ; LCD1.6@3542.17,2558.07 ccw(c3513.37,2529.27) 3513.37,2570 ccw(c3513.37,2610.73) LCD1.6@3542.17,2581.93
NetLCD1_16: LCD1.16 LCD.0 LCD.2 | length 3590
  Bottom Layer w15: LCD.0 LCD.2 3515,390 3560,435 LCD1.16 ; LCD.0@1882.8,378.07 cw(c1911.6,349.27) 1911.6,390 cw(c1911.6,430.73) LCD.0@1882.8,401.93 ; LCD.0@1893.41,367.46 cw(c1947.82,313.06) 1947.82,390 cw(c1947.82,466.94) LCD.0@1893.41,412.54 ; LCD.2@2092.43,367.46 ccw(c2038.03,313.06) 2038.03,390 ccw(c2038.03,466.94) LCD.2@2092.43,412.54 ; LCD.2@2103.04,378.07 ccw(c2074.24,349.27) 2074.24,390 ccw(c2074.24,430.73) LCD.2@2103.04,401.93 ; LCD.2@2142.64,378.07 cw(c2171.44,349.27) 2171.44,390 cw(c2171.44,430.73) LCD.2@2142.64,401.93 ; LCD.2@2153.25,367.46 cw(c2207.66,313.06) 2207.66,390 cw(c2207.66,466.94) LCD.2@2153.25,412.54 ; LCD1.16@3537.46,1547.46 cw(c3483.06,1493.06) 3560,1493.06 cw(c3636.94,1493.06) LCD1.16@3582.54,1547.46 ; LCD1.16@3548.07,1558.07 cw(c3519.27,1529.27) 3560,1529.27 cw(c3600.73,1529.27) LCD1.16@3571.93,1558.07
NetM1_21: >.0 >.2 M1.21 | length 1275.6
  Bottom Layer w15: >.0 >.2 2000,667.16 M1.21 ; >.0@1482.8,378.07 cw(c1511.6,349.27) 1511.6,390 cw(c1511.6,430.73) >.0@1482.8,401.93 ; >.0@1493.41,367.46 cw(c1547.82,313.06) 1547.82,390 cw(c1547.82,466.94) >.0@1493.41,412.54 ; >.2@1692.43,367.46 ccw(c1638.03,313.06) 1638.03,390 ccw(c1638.03,466.94) >.2@1692.43,412.54 ; >.2@1703.04,378.07 ccw(c1674.24,349.27) 1674.24,390 ccw(c1674.24,430.73) >.2@1703.04,401.93 ; >.2@1730.72,421.87 ccw(c1730.72,479.8) 1771.68,438.84 ; >.2@1747.59,390 cw(c1807.32,390) 1765.08,432.24 ; >.2@1762.59,390 cw(c1858.54,390) 1790.69,457.85 ; 1960.39,627.55 ccw(c1917.93,670) M1.21@1977.97,670 ; 1967.25,634.41 cw(c2000,601.65) M1.21@2000,647.97
NetM1_23: <.0 <.2 M1.23 | length 2156.8
  Bottom Layer w15: <.0 <.2 1002.84,470 1340,470 1740,870 M1.23 ; <.0@682.8,378.07 cw(c711.6,349.27) 711.6,390 cw(c711.6,430.73) <.0@682.8,401.93 ; <.0@693.41,367.46 cw(c747.82,313.06) 747.82,390 cw(c747.82,466.94) <.0@693.41,412.54 ; <.2@892.43,367.46 ccw(c838.03,313.06) 838.03,390 ccw(c838.03,466.94) <.2@892.43,412.54 ; <.2@903.04,378.07 ccw(c874.24,349.27) 874.24,390 ccw(c874.24,430.73) <.2@903.04,401.93 ; <.2@930.72,421.87 ccw(c930.72,479.8) 971.68,438.84 ; <.2@947.59,390 cw(c1007.32,390) 965.08,432.24 ; <.2@962.59,390 cw(c1058.54,390) 990.69,457.85 ; M1.23@1984.42,854.42 ccw(c1946.82,816.82) 1946.82,870 ccw(c1946.82,923.18) M1.23@1984.42,885.58
NetM1_24: M1.24 Mode.0 Mode.2 | length 2598.2
  Bottom Layer w15: Mode.0 Mode.2 647.84,515 1315,515 1770,970 M1.24 ; Mode.0@282.8,378.07 cw(c311.6,349.27) 311.6,390 cw(c311.6,430.73) Mode.0@282.8,401.93 ; Mode.0@293.41,367.46 cw(c347.82,313.06) 347.82,390 cw(c347.82,466.94) Mode.0@293.41,412.54 ; Mode.2@492.43,367.46 ccw(c438.03,313.06) 438.03,390 ccw(c438.03,466.94) Mode.2@492.43,412.54 ; Mode.2@503.04,378.07 ccw(c474.24,349.27) 474.24,390 ccw(c474.24,430.73) Mode.2@503.04,401.93 ; Mode.2@530.72,421.87 ccw(c530.72,479.8) 571.68,438.84 ; Mode.2@547.59,390 cw(c607.32,390) 565.08,432.24 ; Mode.2@562.59,390 cw(c658.54,390) 590.69,457.85 ; M1.24@1984.42,954.42 ccw(c1946.82,916.82) 1946.82,970 ccw(c1946.82,1023.18) M1.24@1984.42,985.58
NetQ1_2: Q1.2 R3.2 | length 447.3
  Bottom Layer w15: Q1.2 R3.2 ; Q1.2@428.3,1361.38 cw(c449.1,1340.58) 449.1,1370 cw(c449.1,1399.42) Q1.2@428.3,1378.62 ; R3.2@710.82,1355.82 ccw(c676.57,1321.57) 676.57,1370 ccw(c676.57,1418.43) R3.2@710.82,1384.18
OUTPUT1: L1.2 O1.1 O1.2 | length 1299.2
  Bottom Layer w15: O1.1 O1.2 833,2465 978,2320 L1.2 ; O1.1@155.58,2449.42 cw(c193.18,2411.82) 193.18,2465 cw(c193.18,2518.18) O1.1@155.58,2480.58 ; O1.2@224.42,2449.42 ccw(c186.82,2411.82) 186.82,2465 ccw(c186.82,2518.18) O1.2@224.42,2480.58 ; O1.2@255.58,2449.42 cw(c293.18,2411.82) 293.18,2465 cw(c293.18,2518.18) O1.2@255.58,2480.58 ; L1.2@1029.42,2304.42 ccw(c991.82,2266.82) 991.82,2320 ccw(c991.82,2373.18) L1.2@1029.42,2335.58
OUTPUT2: L1.3 O2.1 O2.2 | length 1528.2
  Bottom Layer w15: O2.1 O2.2 749,2585 964,2370 L1.3 ; O2.1@155.58,2569.42 cw(c193.18,2531.82) 193.18,2585 cw(c193.18,2638.18) O2.1@155.58,2600.58 ; O2.2@224.42,2569.42 ccw(c186.82,2531.82) 186.82,2585 ccw(c186.82,2638.18) O2.2@224.42,2600.58 ; O2.2@255.58,2569.42 cw(c293.18,2531.82) 293.18,2585 cw(c293.18,2638.18) O2.2@255.58,2600.58 ; L1.3@1229.42,2354.42 ccw(c1191.82,2316.82) 1191.82,2370 ccw(c1191.82,2423.18) L1.3@1229.42,2385.58
RST: C3.2 M1.9 R5.2 S6.1 S6.3 | length 1956.3
  Bottom Layer w15: S6.1 S6.3 830,1868.9 851.1,1890 C3.2 1080,1770 R5.2 M1.9 ; S6.1@482.8,1856.97 cw(c511.6,1828.17) 511.6,1868.9 cw(c511.6,1909.63) S6.1@482.8,1880.83 ; S6.1@493.41,1846.36 cw(c547.82,1791.96) 547.82,1868.9 cw(c547.82,1945.84) S6.1@493.41,1891.43 ; S6.3@692.43,1846.36 ccw(c638.03,1791.96) 638.03,1868.9 ccw(c638.03,1945.84) S6.3@692.43,1891.43 ; S6.3@703.04,1856.97 ccw(c674.24,1828.17) 674.24,1868.9 ccw(c674.24,1909.63) S6.3@703.04,1880.83 ; S6.3@742.64,1856.97 cw(c771.44,1828.17) 771.44,1868.9 cw(c771.44,1909.63) S6.3@742.64,1880.83 ; S6.3@753.25,1846.36 cw(c807.66,1791.96) 807.66,1868.9 cw(c807.66,1945.84) S6.3@753.25,1891.43 ; C3.2@944.09,1874.09 ccw(c905.68,1835.68) 905.68,1890 ccw(c905.68,1944.32) C3.2@944.09,1905.91 ; C3.2@960,1867.5 cw(c960,1813.18) 998.41,1851.59 cw(c1036.82,1890) C3.2@982.5,1890 ; R5.2@1245.82,1755.82 ccw(c1211.57,1721.57) 1211.57,1770 ccw(c1211.57,1818.43) R5.2@1245.82,1784.18 ; R5.2@1274.18,1755.82 cw(c1308.43,1721.57) 1308.43,1770 cw(c1308.43,1818.43) R5.2@1274.18,1784.18 ; M1.9@1384.42,1754.42 ccw(c1346.82,1716.82) 1346.82,1770 ccw(c1346.82,1823.18) M1.9@1384.42,1785.58
RX: M1.10 RX.1 RX.2 RX.3 | length 2299.1
  Bottom Layer w15: RX.1 RX.2 RX.3 786,2345 1109,2022 1421,2022 1448,1995 1448,1718 M1.10 ; RX.1@155.58,2329.42 cw(c193.18,2291.82) 193.18,2345 cw(c193.18,2398.18) RX.1@155.58,2360.58 ; RX.2@224.42,2329.42 ccw(c186.82,2291.82) 186.82,2345 ccw(c186.82,2398.18) RX.2@224.42,2360.58 ; RX.2@255.58,2329.42 cw(c293.18,2291.82) 293.18,2345 cw(c293.18,2398.18) RX.2@255.58,2360.58 ; RX.3@324.42,2329.42 ccw(c286.82,2291.82) 286.82,2345 ccw(c286.82,2398.18) RX.3@324.42,2360.58 ; RX.3@355.58,2329.42 cw(c393.18,2291.82) 393.18,2345 cw(c393.18,2398.18) RX.3@355.58,2360.58 ; M1.10@1400,1692.03 ccw(c1400,1745.21) 1437.6,1707.6 ccw(c1475.21,1670) M1.10@1422.03,1670
SCL: E1.6 M1.13 R1.1 | length 1134.3
  Top Layer w15: R1.1@860.06,1700 ccw(c908.49,1700) 874.24,1665.76 ; R1.1 870,1670 E1.6 ; R1.1@875.06,1700 ccw(c959.7,1700) 899.85,1640.15 ; R1.1@890.06,1700 ccw(c1010.91,1700) 925.46,1614.54 ; E1.6@1147.97,1370 ccw(c1094.79,1370) 1132.4,1407.6 ccw(c1170,1445.21) E1.6@1170,1392.03
  Bottom Layer w15: E1.6 M1.13 ; E1.6@1185.58,1354.42 cw(c1223.18,1316.82) 1223.18,1370 cw(c1223.18,1423.18) E1.6@1185.58,1385.58 ; M1.13@1384.42,1354.42 ccw(c1346.82,1316.82) 1346.82,1370 ccw(c1346.82,1423.18) M1.13@1384.42,1385.58
SDA: E1.5 M1.14 R2.1 | length 549.2
  Bottom Layer w15: E1.5 R2.1 M1.14 ; E1.5@1185.58,1254.42 cw(c1223.18,1216.82) 1223.18,1270 cw(c1223.18,1323.18) E1.5@1185.58,1285.58 ; R2.1@1285.82,1255.82 ccw(c1251.57,1221.57) 1251.57,1270 ccw(c1251.57,1318.43) R2.1@1285.82,1284.18 ; R2.1@1314.18,1255.82 cw(c1348.43,1221.57) 1348.43,1270 cw(c1348.43,1318.43) R2.1@1314.18,1284.18 ; M1.14@1384.42,1254.42 ccw(c1346.82,1216.82) 1346.82,1270 ccw(c1346.82,1323.18) M1.14@1384.42,1285.58
TX: M1.11 TX.1 TX.2 TX.3 | length 2337
  Bottom Layer w15: TX.1 TX.2 ; TX.1@155.58,2209.42 cw(c193.18,2171.82) 193.18,2225 cw(c193.18,2278.18) TX.1@155.58,2240.58 ; TX.2@224.42,2240.58 cw(c186.82,2278.18) 186.82,2225 cw(c186.82,2171.82) 224.42,2209.42 cw(c186.82,2171.82) 240,2171.82 cw(c293.18,2171.82) 255.58,2209.42 cw(c293.18,2171.82) 293.18,2225 cw(c293.18,2278.18) TX.2@255.58,2240.58 ; TX.3@324.42,2209.42 ccw(c286.82,2171.82) 286.82,2225 ccw(c286.82,2278.18) TX.3@324.42,2240.58 ; TX.3 TX.2 ; M1.11@1377.97,1570 ccw(c1324.79,1570) 1362.4,1607.6 ccw(c1400,1645.21) M1.11@1400,1592.03 ; M1.11 1341,1629 487,1629 240,1876 TX.2
VCC: 5V.1 5V.2 5V.3 A1.3 C3.1 C4.1 C5.1 D1.1 E1.8 L1.4 L1.6 L1.9 LCD1.2 LCD1.15 M1.31 M1.40 P1.1 Q1.1 R1.2 R2.2 RP1.1 S6.0 S6.2 | length 13588.5
  Top Layer w20: 395.76,1453.63 ccw(c433.63,1453.63) Q1.1@406.85,1426.85 ; 399.7,1986.7 ccw(c336.78,2049.61) S6.0@425.76,2049.9 ; Q1.1 395.76,1424.24 395.76,1982.76 S6.0 ; 418.43,2005.43 cw(c455.13,1968.73) S6.0@455.13,2020.63 ; C3.1@945.86,2004.14 ccw(c911.72,2038.28) 960,2038.28 ccw(c1008.28,2038.28) C3.1@974.14,2004.14 ; C3.1@960,1970 cw(c960,1921.72) 994.14,1955.86 cw(c1028.28,1990) C3.1@980,1990 ; L1.4@1025.47,2420 cw(c978.33,2420) 1011.66,2386.66 cw(c1045,2353.33) L1.4@1045,2400.47 ; L1.4@1031.19,2433.81 ccw(c997.86,2467.14) 1045,2467.14 ccw(c1092.14,2467.14) L1.4@1058.81,2433.81 ; L1.6@1031.19,2506.19 cw(c997.86,2472.86) 1045,2472.86 cw(c1092.14,2472.86) L1.6@1058.81,2506.19 ; L1.6 L1.4 960,2335 C3.1 1170,1780 R1.2 E1.8 ; E1.8@1156.19,1583.81 ccw(c1122.86,1617.14) 1170,1617.14 ccw(c1217.14,1617.14) E1.8@1183.81,1583.81 ; R1.2@1157.58,1687.58 cw(c1127.61,1657.61) 1170,1657.61 cw(c1212.39,1657.61) R1.2@1182.42,1687.58 ; R1.2@1157.58,1712.42 ccw(c1127.61,1742.39) 1170,1742.39 ccw(c1212.39,1742.39) R1.2@1182.42,1712.42
  Bottom Layer w15: 5V.1 5V.2 5V.3@320,2705 ; 5V.1@155.58,2689.42 cw(c193.18,2651.82) 193.18,2705 cw(c193.18,2758.18) 5V.1@155.58,2720.58 ; 5V.2@224.42,2689.42 ccw(c186.82,2651.82) 186.82,2705 ccw(c186.82,2758.18) 5V.2@224.42,2720.58 ; 5V.2@255.58,2689.42 cw(c293.18,2651.82) 293.18,2705 cw(c293.18,2758.18) 5V.2@255.58,2720.58 ; 5V.3@324.42,2689.42 ccw(c286.82,2651.82) 286.82,2705 ccw(c286.82,2758.18) 5V.3@324.42,2720.58
  Bottom Layer w20: 5V.3@320,2705 5V.3 540,2725 A1.3 840,2725 L1.6 1195,2670 L1.9 ; 5V.3@352.37,2720.11 ccw(c382.22,2756.6) 386.91,2709.69 ccw(c391.6,2662.78) 5V.3@355.11,2692.63 ; S6.0 S6.2 900,2050 C3.1 ; S6.0@491.64,2029.23 cw(c541.78,1979.09) 541.78,2050 cw(c541.78,2120.91) S6.0@491.64,2070.77 ; A1.3@686.19,2711.19 ccw(c652.86,2677.86) 652.86,2725 ccw(c652.86,2772.14) A1.3@686.19,2738.81 ; S6.2@694.2,2029.23 ccw(c644.06,1979.09) 644.06,2050 ccw(c644.06,2120.91) S6.2@694.2,2070.77 ; A1.3@713.81,2711.19 cw(c747.14,2677.86) 747.14,2725 cw(c747.14,2772.14) A1.3@713.81,2738.81 ; S6.2@751.48,2029.23 cw(c801.62,1979.09) 801.62,2050 cw(c801.62,2120.91) S6.2@751.48,2070.77 ; C3.1@940,1990 ccw(c891.72,1990) 925.86,2024.14 ccw(c960,2058.28) C3.1@960,2010 ; L1.6@1025.47,2520 ccw(c978.33,2520) 1011.66,2553.34 ccw(c1045,2586.67) 1045,2539.53 ccw(c1045,2586.67) 1078.34,2553.34 ccw(c1111.67,2520) L1.6@1064.53,2520 ; C4.1@1115.86,3185.86 cw(c1081.72,3151.72) 1130,3151.72 cw(c1178.28,3151.72) C4.1@1144.14,3185.86 ; C4.1 1130,2785 L1.9 ; E1.8 R2.2 ; E1.8@1183.81,1556.19 cw(c1217.14,1522.86) 1217.14,1570 cw(c1217.14,1617.14) E1.8@1183.81,1583.81 ; L1.9@1225.47,2670 ccw(c1178.33,2670) 1211.66,2703.34 ccw(c1245,2736.67) L1.9@1245,2689.53 ; L1.9@1231.19,2656.19 ccw(c1197.86,2622.86) 1197.86,2670 ccw(c1197.86,2717.14) L1.9@1231.19,2683.81 ; L1.9@1258.81,2656.19 cw(c1292.14,2622.86) 1292.14,2670 cw(c1292.14,2717.14) L1.9@1258.81,2683.81 ; R2.2@1287.58,1557.58 ccw(c1257.61,1527.61) 1257.61,1570 ccw(c1257.61,1612.39) R2.2@1287.58,1582.42 ; 1537.57,2717.57 ccw(c1435.15,2820) D1.1@1580,2820 ; 1571.72,2751.72 ccw(c1503.43,2820) D1.1@1600,2820 ; D1.1@1691.21,2798.79 cw(c1742.43,2747.57) 1742.43,2820 cw(c1742.43,2892.43) D1.1@1691.21,2841.21 ; RP1.1@1886.69,2980 cw(c1806.28,2980) 1863.14,2923.14 cw(c1920,2866.28) RP1.1@1920,2946.69 ; RP1.1@1896.45,2956.45 cw(c1839.59,2899.59) 1920,2899.59 cw(c2000.41,2899.59) RP1.1@1943.55,2956.45 ; RP1.1@1896.45,3003.55 ccw(c1839.59,3060.41) 1920,3060.41 ccw(c2000.41,3060.41) RP1.1@1943.55,3003.55 ; C5.1@1956.38,3300 cw(c1923.49,3300) 1946.75,3276.75 cw(c1970,3253.49) C5.1@1970,3286.38 ; C5.1 1920,3250 RP1.1 ; M1.31@1980.47,1670 ccw(c1933.33,1670) 1966.66,1703.34 ccw(c2000,1736.67) M1.31@2000,1689.53 ; M1.40@2000,2550.47 ccw(c2000,2503.33) 1966.66,2536.66 ccw(c1933.33,2570) 1980.47,2570 ccw(c1933.33,2570) 1966.66,2603.34 ccw(c2000,2636.67) M1.40@2000,2589.53 ; M1.31@2013.81,1656.19 cw(c2047.14,1622.86) 2047.14,1670 cw(c2047.14,1717.14) M1.31@2013.81,1683.81 ; M1.40@2013.81,2556.19 cw(c2047.14,2522.86) 2047.14,2570 cw(c2047.14,2617.14) M1.40@2013.81,2583.81 ; P1.1@2106.19,2556.19 ccw(c2072.86,2522.86) 2072.86,2570 ccw(c2072.86,2617.14) P1.1@2106.19,2583.81 ; P1.1 M1.40 ; LCD1.15@3533.33,1649.23 ccw(c3483.19,1599.09) 3483.19,1670 ccw(c3483.19,1740.91) LCD1.15@3533.33,1690.77 ; LCD1.2 3560,2959.87 3625.28,2894.59 3625.28,1735.28 LCD1.15 M1.31 1950.47,1719.53 1950.47,2520.47 M1.40 ; LCD1.15@3565.91,1699.37 ccw(c3565.91,1756.02) 3605.96,1715.96 ; LCD1.2@3565.91,2940.63 cw(c3565.91,2908.44) 3588.67,2931.2 ; LCD1.2@3575.21,2968.9 ccw(c3619.93,2963.62) 3588.09,2931.78 ; LCD1.2@3595.07,2966.56 ccw(c3672.1,2957.46) 3617.25,2902.61 ; LCD1.15@3595.28,1670 cw(c3680.44,1670) 3620.22,1730.22 ; L1.9 1490,2670 D1.1 1760,2820 RP1.1 ; RP1.1 1920,2650 M1.40
VO: LCD1.3 RP1.2 | length 1908.4
  Bottom Layer w15: RP1.2@2025,2875 2798,2870 LCD1.3 ; RP1.2@2034.81,2894.62 ccw(c2082.63,2941.82) 2082.19,2874.63 ; RP1.2@2045.16,2854.52 cw(c2093.97,2805.07) 2094.42,2874.55 ; RP1.2@2045.48,2905.16 ccw(c2119.07,2977.8) 2118.4,2874.4 ; LCD1.3@3531.56,2847.46 ccw(c3477.15,2793.06) 3477.15,2870 ccw(c3477.15,2946.94) LCD1.3@3531.56,2892.54 ; LCD1.3@3542.17,2858.07 ccw(c3513.37,2829.27) 3513.37,2870 ccw(c3513.37,2910.73) LCD1.3@3542.17,2881.93
VSS: 3V3.1 3V3.2 3V3.3 A1.2 | length 1061.2
  Bottom Layer w15: 3V3.1 3V3.2 3V3.3 A1.2 ; 3V3.1@155.58,2809.42 cw(c193.18,2771.82) 193.18,2825 cw(c193.18,2878.18) 3V3.1@155.58,2840.58 ; 3V3.2@224.42,2809.42 ccw(c186.82,2771.82) 186.82,2825 ccw(c186.82,2878.18) 3V3.2@224.42,2840.58 ; 3V3.2@255.58,2809.42 cw(c293.18,2771.82) 293.18,2825 cw(c293.18,2878.18) 3V3.2@255.58,2840.58 ; 3V3.3@324.42,2809.42 ccw(c286.82,2771.82) 286.82,2825 ccw(c286.82,2878.18) 3V3.3@324.42,2840.58 ; 3V3.3@355.58,2809.42 cw(c393.18,2771.82) 393.18,2825 cw(c393.18,2878.18) 3V3.3@355.58,2840.58 ; A1.2@684.42,2809.42 ccw(c646.82,2771.82) 646.82,2825 ccw(c646.82,2878.18) A1.2@684.42,2840.58
pads on no net: L1.10 L1.11 L1.12 L1.13 L1.14 L1.15 M1.3 M1.4 M1.5 M1.6 M1.7 M1.8 M1.12 M1.15 M1.17 M1.25 M1.29 M1.30
copper on no net: | length 14800
  Top Layer w10: 0,0 0,3500 3900,3500 3900,0 0,0

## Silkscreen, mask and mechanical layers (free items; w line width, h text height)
Top Overlay:
  text "+" at 885,3230 h100 r270
  text "+" at 990,2125 h80 r270
  text "Triskelion" at 3705,2100 h180 r270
